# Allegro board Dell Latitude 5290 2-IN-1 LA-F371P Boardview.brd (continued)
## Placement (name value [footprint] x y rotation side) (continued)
PR280  100K_0402_5%  [R_0402]  148.26 120.72 0 top
PR281  100K_0402_5%  [R_0402]  148.13 117.16 0 top
PR282  549K_0402_1%  [R_0402]  145.67 117.78 90 top
PR283  100K_0402_5%  [R_0402]  148.51 125.03 0 top
PR284  100K_0402_5%  [R_0402]  149.43 124.14 180 top
PR285  1M_0402_1%  [R_0402]  145.68 119.64 180 top
PR300  0.01_1206_1%  [R_1206_4P-D]  123.97 99.57 180 top
PR301  3.3_0402_1%  [R_0402]  129.21 127.19 0 bottom
PR302  3.3_0402_1%  [R_0402]  129.21 128.08 0 bottom
PR303  2_1206_5%  [R_1206]  126.87 131.13 0 bottom
PR305  442K_0402_1%  [R_0402]  132.89 132.65 0 bottom
PR306  2.2_0603_5%  [R_0603]  129.73 125.92 0 bottom
PR307  100K_0402_1%  [R_0402]  133.81 131.76 180 bottom
PR308  4.7_0402_5%  [R_0402]  132.77 129.61 0 top
PR309  2_1206_5%  [R_1206]  135.95 131.13 180 top
PR310  0.005_1206_1%  [R_1206_4P-D]  139.31 119.06 0 top
PR311  2.2_0603_5%  [R_0603]  133.73 122.56 270 bottom
PR312  154K_0402_1%  [R_0402]  153.56 123.8 180 top
PR313  0_0402_5%  [R_0402]  136.59 131.71 270 bottom
PR314  0_0402_5%  [R_0402]  137.48 131.71 270 bottom
PR315  75_0402_5%  [R_0402]  138.37 131.71 270 bottom
PR316  4.7_1206_5%  [R_1206]  134.37 104.52 270 bottom
PR317  4.7_1206_5%  [R_1206]  127.51 116.71 90 bottom
PR318  0_0402_5%  [R_0402]  135.13 123.08 270 top
PR319  100K_0402_1%  [R_0402]  134.92 129.54 0 top
PR322  105K_0402_1%  [R_0402]  139.24 128.59 0 bottom
PR323  2.2_0402_1%  [R_0402]  137.1 120.89 90 bottom
PR324  2.2_0402_1%  [R_0402]  137.99 120.89 90 bottom
PR325  1M_0402_1%  [R_0402]  140.16 130.37 180 bottom
PR327  499_0402_1%  [R_0402]  139.26 126.76 270 bottom
PR328  1K_0402_1%  [R_0402]  31.02 123.3 270 bottom
PR329  0_0402_5%  [R_0402]  139.26 124.98 270 bottom
PR330  100_0402_1%  [R_0402]  139.24 124.53 0 top
PR331  0_0402_5%  [R_0402]  132.89 130.86 0 bottom
PR332  0_0402_5%  [R_0402]  140.16 129.48 180 bottom
PR333  10K_0402_5%  [R_0402]  53.35 158.72 270 bottom
PR334  0_0402_5%  [R_0402]  135.59 131.75 270 bottom
PR336  1M_0402_1%  [R_0402]  154.69 128.34 270 top
PR338  0_0402_5%  [R_0402]  152.62 128.46 0 top
PR341  0_0402_5%  [R_0402]  136.72 129.17 270 top
PR342  0_0402_5%  [R_0402]  153.96 118.71 90 top
PR343  0_0402_5%  [R_0402]  155.28 118.71 90 top
PR345  0_0402_5%  [R_0402]  154.69 123.59 90 top
PR346  100K_0402_1%  [R_0402]  158.41 124.47 270 top
PR347  1M_0402_1%  [R_0402]  152.6 122.59 270 top
PR351  0_0402_5%  [R_0402]  158.41 126.28 270 top
PR400  10_0603_5%  [R_0603]  70.68 74.87 180 top
PR401  0_0402_5%  [R_0402]  79.49 81.83 0 top
PR402  0_0402_5%  [R_0402]  77.71 82.72 0 top
PR403  0_0402_5%  [R_0402]  78.55 80.35 180 top
PR404  0_0402_5%  [R_0402]  77.71 83.61 0 top
PR405  523K_0402_1%  [R_0402]  78.55 77.92 180 top
PR406  43K_0201_1%  [R_0201]  78.46 78.69 180 top
PR407  10K_0402_1%  [R_0402]  70.31 87.95 180 top
PR408  1M_0402_1%  [R_0402]  69.39 85.28 0 top
PR409  0_0402_5%  [R0402_0OHM]  69.39 87.06 0 top
PR410  1M_0402_1%  [R_0402]  69.39 79.06 0 top
PR411  0_0402_5%  [R_0402]  79.49 82.72 0 top
PR412  45.3K_0402_1%  [R_0402]  70.31 79.95 180 top
PR413  1M_0402_1%  [R_0402]  77.64 79.45 0 top
PR414  953K_0402_1%  [R_0402]  70.31 80.84 180 top
PR415  118K_0402_1%  [R_0402]  70.31 81.73 180 top
PR416  0_0402_5%  [R0402_0OHM]  70.31 84.39 180 top
PR417  0_0402_5%  [R0402_0OHM]  72.21 85.92 180 top
PR418  0_0402_5%  [R_0402]  72.21 85.03 180 top
PR419  0_0402_5%  [R_0402]  70.31 83.5 180 top
PR420  0_0402_5%  [R_0402]  73.96 85.92 0 top
PR500  0_0402_5%  [R0402_0OHM]  123.33 119.83 180 top
PR501  3.3_0603_1%  [R_0603]  121.86 115.25 0 top
PR502  4.7_0805_5%  [R_0805]  119.25 114.78 90 bottom
PR503  100K_0402_5%  [R_0402]  116.4 119.5 90 top
PR504  0_0402_5%  [R_0402]  123.32 118.04 90 top
PR505  2.2K_0402_1%  [R_0402]  123.33 117.98 180 bottom
PR506  0_0402_5%  [R_0402]  41.71 150.69 0 top
PR507  3.3_0603_1%  [R_0603]  42.86 155.39 180 top
PR508  4.7_0805_5%  [R_0805]  45.5 156.15 0 bottom
PR509  100K_0402_5%  [R_0402]  48.9 153.4 90 top
PR510  0_0402_5%  [R_0402]  41.71 151.58 0 top
PR511  0_0402_5%  [R0402_0OHM]  123.9 146.29 180 top
PR512  3.3_0603_1%  [R_0603]  122.56 141.59 0 top
PR513  4.7_0805_5%  [R_0805]  118.36 141.63 90 bottom
PR514  100K_0402_5%  [R_0402]  117.35 147.23 90 top
PR515  0_0402_5%  [R_0402]  123.89 144.45 90 top
PR516  100K_0402_1%  [R_0402]  122.43 118.95 270 top
PR517  100K_0402_1%  [R_0402]  42.62 152.47 180 top
PR518  100K_0402_1%  [R_0402]  123 145.37 270 top
PR519  0_0402_5%  [R_0402]  116.4 115.56 90 top
PR600  75_0402_5%  [R_0402]  108.75 120.16 270 bottom
PR601  2.2_0603_5%  [R_0603]  110.68 117.16 0 top
PR602  4.7_0805_5%  [R_0805]  107.19 118.72 90 bottom
PR603  100K_0402_1%  [R_0402]  111.84 119.19 180 top
PR604  100K_0402_1%  [R_0402]  110.92 120.08 0 top
PR605  0_0402_5%  [R_0402]  109.09 123.33 270 bottom
PR606  100K_0402_5%  [R_0402]  103.56 121.6 0 top
PR607  1M_0402_1%  [R_0402]  108.2 122.42 90 bottom
PR608  0_0402_5%  [R_0402]  109.98 123.33 270 bottom
PR609  150K_0402_1%  [R_0402]  110.92 120.97 0 top
PR610  0_0402_5%  [R0402_0OHM]  104.47 122.49 180 top
PR611  0_0402_5%  [R_0402]  111.84 123.64 180 top
PR612  1M_0402_1%  [R_0402]  110.92 122.75 0 top
PR700  75K_0402_1%  [R_0402]  133.73 137.66 90 top
PR701  1M_0402_1%  [R_0402]  132.84 138.57 270 top
PR702  4.7_0603_5%  [R_0603]  127.83 143.13 90 bottom
PR703  0_0603_5%  [R_0603]  125.35 142.18 90 top
PR704  14K_0402_1%  [R_0402]  132.79 141.73 180 bottom
PR705  100K_0402_5%  [R_0402]  129.46 137.1 0 top
PR706  20K_0402_1%  [R_0402]  131.88 139.96 0 bottom
PR707  100K_0402_5%  [R_0402]  132.85 140.34 180 top
PR708  0_0402_5%  [R_0402]  132.85 139.45 180 top
PR709  0_0402_5%  [R0402_0OHM]  132.85 141.23 180 top
PR720  0_0402_5%  [R_0402]  142.82 141.8 180 top
PR721  0_0402_5%  [R_0402]  142.82 142.69 180 top
PR722  412K_0402_1%  [R_0402]  135.05 142.43 0 top
PR723  4.7_0603_5%  [R_0603]  139 144.34 180 bottom
PR724  324K_0402_1%  [R_0402]  135.95 141.56 270 top
PR725  100K_0402_5%  [R_0402]  134.11 142.13 270 top
PR726  0_0402_5%  [R0402_0OHM]  135.06 140.64 90 top
PR727  0_0402_5%  [R_0402]  105.36 98.36 180 top
PR728  0_0402_5%  [R_0402]  104.44 97.47 0 top
PR729  412K_0402_1%  [R_0402]  112.22 96.33 180 top
PR730  4.7_0805_5%  [R_0805]  106.93 93.12 270 top
PR731  324K_0402_1%  [R_0402]  111.32 95.45 270 top
PR732  100K_0402_5%  [R_0402]  111.3 93.66 0 top
PR733  0_0402_5%  [R0402_0OHM]  111.3 97.22 0 top
PR734  100K_0402_5%  [R_0402]  119 124.6 270 top
PR735  100K_0402_5%  [R_0402]  46.43 142.43 180 top
PR800  10K_0402_1%  [R_0402]  123.19 131.71 270 top
PR801  0_0402_5%  [R_0402]  122.3 131.71 270 top
PR803  1M_0402_1%  [R_0402]  124.97 130.8 90 top
PR804  10K_0402_1%  [R_0402]  127.71 126.18 180 top
PR805  10K_0402_1%  [R_0402]  126.06 126.05 180 bottom
PR806  4.7_0603_5%  [R_0603]  120.97 126.18 0 bottom
PR807  100_0402_1%  [R_0402]  120.27 123.69 90 top
PR808  10K_0402_1%  [R_0402]  124.28 126.05 180 bottom
PR809  10K_0402_1%  [R_0402]  126.8 125.29 0 top
PR810  0_0402_5%  [R0402_0OHM]  121.16 124.6 270 top
PR811  0_0402_5%  [R0402_0OHM]  122.05 124.6 270 top
PR812  100_0402_1%  [R_0402]  122.94 124.6 270 top
PR813  10K_0402_1%  [R_0402]  48.45 147.75 90 top
PR814  0_0402_5%  [R_0402]  49.34 148.67 270 top
PR815  130K_0402_1%  [R_0402]  51.19 149.54 180 top
PR816  1M_0402_1%  [R_0402]  50.28 148.66 0 top
PR817  10K_0402_1%  [R_0402]  52.83 140.83 90 top
PR818  10K_0402_1%  [R_0402]  53.54 142.69 180 top
PR819  4.7_0603_5%  [R_0603]  48.13 145.67 90 bottom
PR820  10K_0402_1%  [R_0402]  51.05 141.75 270 top
PR821  10K_0402_1%  [R_0402]  52.63 144.46 0 top
PR822  0_0402_5%  [R_0402]  53.54 143.58 180 top
PR823  0_0402_5%  [R_0402]  51.94 140.83 90 top
PR824  0_0402_5%  [R0402_0OHM]  48.4 141.73 180 top
PR825  100K_0402_1%  [R_0402]  49.28 141.75 270 top
PR826  0_0402_5%  [R_0402]  124.63 133.16 0 top
PR900  45.3_0402_1%  [R_0402]  63.42 145.98 90 bottom
PR901  75_0402_1%  [R_0402]  59.97 145.98 90 bottom
PR903  0_0402_5%  [R_0402]  62.06 158.92 90 bottom
PR904  0_0402_5%  [R_0402]  62.93 158.92 90 bottom
PR906  0_0402_5%  [R_0402]  64.66 158.94 0 bottom
PR907  0_0402_5%  [R_0402]  65.1 157.18 90 bottom
PR910  1.5K_0402_1%  [R_0402]  60.29 158.47 90 bottom
PR911  1.5K_0402_1%  [R_0402]  59.42 158.47 90 bottom
PR912  1.5K_0402_1%  [R_0402]  58.56 158.47 90 bottom
PR913  1.5K_0402_1%  [R_0402]  57.7 158.47 90 bottom
PR914  1.91K_0402_1%  [R_0402]  61.15 158.92 90 bottom
PR915  2.49K_0402_1%  [R_0402]  63.82 159.83 270 bottom
PR916  0_0402_5%  [R_0402]  54.76 152.7 0 bottom
PR917  10K_0402_1%  [R_0402]  56.51 147.73 90 bottom
PR918  10K_0402_1%  [R_0402]  57.38 147.73 90 bottom
PR919  10K_0402_1%  [R_0402]  58.24 147.73 90 bottom
PR920  10K_0402_1%  [R_0402]  54.76 151.83 0 bottom
PR921  0_0402_5%  [R_0402]  55.63 149.51 0 bottom
PR922  0_0402_5%  [R_0402]  56.45 145.98 90 bottom
PR923  0_0402_5%  [R_0402]  57.34 145.98 90 bottom
PR924  0_0402_5%  [R_0402]  63.42 148.64 270 bottom
PR925  100_0402_1%  [R_0402]  62.56 145.98 90 bottom
PR926  0_0402_5%  [R_0402]  60.83 147.73 90 bottom
PR927  49.9_0402_1%  [R_0402]  62.56 147.73 90 bottom
PR928  10_0402_1%  [R_0402]  61.7 147.73 90 bottom
PR929  0_0402_5%  [R_0402]  61.7 145.98 90 bottom
PR930  0_0402_5%  [R_0402]  60.83 145.98 90 bottom
PR931  1.91K_0402_1%  [R_0402]  59.11 147.73 90 bottom
PR932  0_0402_5%  [R_0402]  59.97 147.73 90 bottom
PR933  75_0402_5%  [R_0402]  58.24 145.98 90 bottom
PR934  10K_0402_1%  [R_0402]  59.11 145.98 90 bottom
PR935  0_0402_5%  [R_0402]  64.29 147.73 90 bottom
PR936  0_0402_5%  [R_0402]  66.32 150.21 180 bottom
PR937  10K_0402_1%  [R_0402]  65.42 148.42 90 bottom
PR938  5.23K_0402_1%  [R_0402]  55.94 156.72 90 bottom
PR939  0_0402_5%  [R_0402]  53.9 149.51 0 bottom
PR940  10K_0402_1%  [R_0402]  55.65 148.63 180 bottom
PR941  118K_0402_1%  [R_0402]  68.1 154.91 180 bottom
PR942  133K_0402_1%  [R_0402]  55.1 159.58 180 bottom
PR943  2M_0402_5%  [R_0402]  56.83 158.47 90 bottom
PR944  121K_0402_1%  [R_0402]  68.1 154.02 180 bottom
PR945  620K_0402_1%  [R_0402]  66.32 151.98 180 bottom
PR946  49.9K_0402_1%  [R_0402]  55.1 156.99 180 bottom
PR947  0_0402_5%  [R_0402]  54.72 154.93 0 bottom
PR948  8.06K_0402_1%  [R_0402]  65.98 157.83 0 bottom
PR949  0_0402_5%  [R_0402]  54.19 158.72 0 bottom
PR950  4.7_0402_5%  [R_0402]  55.65 147.74 180 bottom
PR951  0_0402_5%  [R_0402]  65.41 155.79 0 bottom
PR952  0_0402_5%  [R_0402]  65.41 154.91 0 bottom
PR953  100K_0402_1%  [R_0402]  60.3 160.24 180 bottom
PR954  100K_0402_1%  [R_0402]  64.67 159.83 0 bottom
PR955  100K_0402_1%  [R_0402]  67.31 156.75 0 bottom
PR956  61.9K_0402_1%  [R_0402]  66.32 151.1 180 bottom
PR1101  0_0402_5%  [R_0402]  79.69 159.78 270 top
PR1103  0_0402_5%  [R_0402]  62.8 159.84 270 top
PR1106  4.7_0805_5%  [R_0805]  89.7 157.29 0 top
PR1108  4.7_0805_5%  [R_0805]  72.97 157.18 90 top
PR1117  4.7_0805_5%  [R_0805]  101.33 155.69 0 top
PR1118  0_0402_5%  [R_0402]  93.28 158.83 270 top
PR1125  4.7_0805_5%  [R_0805]  54.55 152.19 270 top
PR1126  0_0402_5%  [R_0402]  52.96 156.29 270 top
PR1200  1K_0402_1%  [R_0402]  94.61 145.34 90 top
PR1201  1K_0402_1%  [R_0402]  110.41 147.19 0 top
PR1202  1K_0402_1%  [R_0402]  56.02 144.21 180 top
PR1203  0_0805_5%  [R_0805]  47.35 149.87 180 bottom
PR1204  0_0603_5%  [R_0603]  53.49 149.09 270 top
PT100  PAD~D  [TPC12]  121.91 101.4 0 top
PT101  PAD~D  [TPC12]  8.01 39.1 180 bottom
PT102  PAD~D  [TPC12]  13.97 32.45 180 bottom
PT103  PAD~D  [TPC12]  152.7 119.39 0 top
PU101  -  [RT9069-33GB_SOT23-5]  16.26 48.73 270 top
PU103  -  [AS331KTR-G1_SOT23-5]  26.54 49.09 270 top
PU104  -  [AS331KTR-G1_SOT23-5]  36.92 41.85 90 top
PU105  -  [AS331KTR-G1_SOT23-5]  34.54 19.12 90 top
PU280  -  [SN74LVC1G123DCUR_VSSOP8]  150 118.19 90 top
PU300  -  [ISL88738HRTZ-T_TQFN32_4X4]  136.78 124.51 90 bottom
PU301  TC7SH08FU_SSOP5  [MC74VHC1G08DFT2G_SC70-5]  155.97 123.75 0 top
PU400  TPS61188ARUYR_QFN28_4X4  [TPS61188ARUYR_QFN28_4X4-S]  75.89 79.3 90 top
PU500  -  [NB680GD-Z_QFN12_2X3]  119.75 118.44 270 top
PU501  -  [NB679AGD-Z_QFN12_2X3]  45.35 153.39 90 top
PU502  -  [NB679GD-Z_QFN12_2X3]  120.32 145.38 270 top
PU600  -  [NB685GQ-Z_QFN16_3X3]  108.18 120.3 270 top
PU700  -  [SY8286RAC_QFN20_3X3]  127.23 141.05 0 top
PU720  TLV62150ARGTR_QFN16_3X3  [TLV62150RGTR_QFN16_3X3-S]  139.78 143.21 180 top
PU721  TLV62150RGTR_QFN16_3X3  [TLV62150RGTR_QFN16_3X3-S]  107.49 94.9 0 top
PU800  TPS62134ARGT_QFN16_3X3  [TPS62134ARGT_QFN16_3X3-S]  122.23 128.27 0 top
PU801  TPS62134DRGT_QFN16_3X3  [TPS62134BRGT_QFN16_3X3-S]  47.98 145.47 0 top
PU900  MP2949AGQKT-0020  [MP2949GU-LF-Z_QFN48_6X6]  58.56 157.22 270 bottom
PU1005  -  [MP86901-CGLT-Z_TQFN21_3X4]  82.85 158.78 90 top
PU1006  -  [MP86901-CGLT-Z_TQFN21_3X4]  65.96 158.81 90 top
PU1107  -  [MP86901-CGLT-Z_TQFN21_3X4]  95.5 156.06 90 top
PU1108  -  [MP86901-AGQT-Z_TQFN13_3X3]  56.09 155.28 90 top
Q1  -  [DMN2400UV-7_SOT-563-6]  119.74 158.35 180 bottom
Q2  -  [MMBT3904WH_SOT323-3]  5.54 164.78 0 top
Q6  -  [MMBT3904WH_SOT323-3]  143.57 113.68 180 bottom
Q7  -  [MMBT3904WH_SOT323-3]  44.83 84.74 180 top
Q8  -  [MMBT3904WH_SOT323-3]  21.97 17.93 180 top
Q9  -  [DMN2400UV-7_SOT-563-6]  155.23 146.5 90 bottom
Q10  DII-DMN65D8LW-7  [SSM3K7002FU_SC70-3]  63.5 100.21 180 bottom
Q11  -  [MMBT3904WH_SOT323-3]  65.75 111.08 180 bottom
Q12  DII-DMN65D8LW-7  [SSM3K7002FU_SC70-3]  25.6 125.25 0 bottom
Q16  DII-DMN65D8LW-7  [SSM3K7002FU_SC70-3]  52.26 85.54 90 top
Q22  DII-DMN65D8LW-7  [SSM3K7002FU_SC70-3]  26.4 135.38 270 bottom
Q25  -  [DMN2400UV-7_SOT-563-6]  28.38 127.14 180 bottom
Q26  -  [DMN2400UV-7_SOT-563-6]  124.88 155.01 90 bottom
Q29  DII-DMN65D8LW-7  [SSM3K7002FU_SC70-3]  33.64 109.46 0 top
Q31  -  [MMBT3904WH_SOT323-3]  45.42 103.68 180 bottom
Q32  DII-DMN65D8LW-7  [SSM3K7002FU_SC70-3]  83.72 73.06 90 top
Q33  SI3457BDV-T1-E3_TSOP6~D  [SI3457BDV-T1-E3_TSOP6]  84.52 75.13 90 top
Q348  DII-DMN65D8LW-7  [SSM3K7002FU_SC70-3]  28.19 93.36 180 bottom
Q349  -  [DMG2301U-7_SOT23-3]  30.68 97.09 90 bottom
Q351  DII-DMN65D8LW-7  [SSM3K7002FU_SC70-3]  66.29 85.33 90 top
Q352  -  [DMG2301U-7_SOT23-3]  56.16 103.51 270 bottom
Q353  DII-DMN65D8LW-7  [SSM3K7002FU_SC70-3]  51.6 104.87 180 bottom
Q354  -  [DMN2400UV-7_SOT-563-6]  126.91 92.06 90 top
Q356  DII-DMN65D8LW-7  [SSM3K7002FU_SC70-3]  47.24 84.77 0 top
Q357  DII-DMN65D8LW-7  [SSM3K7002FU_SC70-3]  24.41 93.38 90 bottom
QC2  -  [DMN66D0LDW-7_SOT363-6]  29.72 37.78 270 top
QC3  -  [DMN66D0LDW-7_SOT363-6]  29.91 25.83 90 top
QE13  -  [DMN66D0LDW-7_SOT363-6]  136.87 137.67 180 top
QE14  -  [DMN66D0LDW-7_SOT363-6]  16.7 102.41 90 bottom
QE15  DII-DMN65D8LW-7  [SSM3K7002FU_SC70-3]  21.59 122.74 0 bottom
QE16  -  [MMBT3904WH_SOT323-3]  17.26 122.35 180 bottom
QR1  -  [DMN2400UFB4-7_DFN1006H4-3]  68.2 29.12 270 bottom
QZ9  -  [DMG2301U-7_SOT23-3]  29.97 101.79 90 bottom
R1  0_0402_1%  [R0402_0OHM]  117.78 171.9 0 top
R2  0_0402_1%  [R0402_0OHM]  117.78 170.88 0 top
R3  100K_0201_5%  [R_0201]  126.36 169.06 90 top
R4  0_0402_1%  [R0402_0OHM]  117.78 168.85 0 top
R5  100K_0201_5%  [R_0201]  127 169.06 90 top
R6  0_0402_1%  [R0402_0OHM]  117.78 169.86 0 top
R7  0_0402_1%  [R0402_0OHM]  117.78 166.69 0 top
R8  0_0402_1%  [R0402_0OHM]  117.78 167.83 0 top
R9  0_0402_1%  [R0402_0OHM]  117.53 156.4 0 top
R11  0_0201_5%  [R0201_0OHM]  125.5 161.81 0 top
R12  0_0402_1%  [R0402_0OHM]  117.53 155.39 0 top
R13  0_0402_1%  [R0402_0OHM]  117.53 158.43 0 top
R14  100K_0201_5%  [R_0201]  126.1 160.59 180 top
R15  100K_0201_5%  [R_0201]  125.44 154.9 0 top
R16  0_0402_1%  [R0402_0OHM]  117.53 157.42 0 top
R17  0_0402_1%  [R0402_0OHM]  117.53 162.5 0 top
R18  0_0402_1%  [R0402_0OHM]  117.53 161.48 0 top
R19  0_0402_1%  [R0402_0OHM]  117.53 160.47 0 top
R20  0_0402_1%  [R0402_0OHM]  117.53 159.45 0 top
R21  0_0402_1%  [R0402_0OHM]  117.53 164.53 0 top
R22  0_0402_1%  [R0402_0OHM]  117.53 163.51 0 top
R23  1K_0201_5%  [R_0201]  6.26 153.48 180 top
R24  1K_0201_5%  [R_0201]  6.39 140.15 180 top
R26  0_0402_1%  [R0402_0OHM]  66.09 138.88 0 top
R27  10K_0402_5%~D  [R_0402]  152.74 137.67 180 top
R28  10K_0402_5%~D  [R_0402]  153.67 139.5 180 top
R29  10K_0402_5%~D  [R_0402]  152.78 135.37 90 top
R30  0_0603_5%  [R0603_0OHM]  128.71 135.32 0 top
R31  100K_0402_5%~D  [R_0402]  122.61 134.05 0 top
R32  100K_0402_5%  [R_0402]  101.66 118.82 270 top
R33  10K_0201_1%  [R_0201]  27.52 112.33 0 top
R35  10K_0201_1%  [R_0201]  34.29 112.41 180 top
R38  0_0402_1%  [R0402_0OHM]  29.79 112.46 180 top
R48  0_0603_5%  [R0603_0OHM]  68.22 104.46 0 top
R50  100K_0402_5%  [R_0402]  31.83 102.94 180 top
R51  1M_0402_5%  [R_0402]  33.45 102.94 0 top
R54  10K_0402_5%  [R_0402]  36.91 100.78 180 top
R56  23.2K_0402_1%  [R_0402]  33.29 96.97 180 top
R57  0_0402_5%  [R_0402]  61.19 86.6 90 top
R59  0_0402_1%  [R0402_0OHM]  59.21 86.37 270 top
R60  0_0402_1%  [R0402_0OHM]  60.22 86.37 270 top
R61  220K_0201_5%  [R_0201]  70.99 87.76 270 top
R64  10K_0402_5%  [R_0402]  61.16 85.74 270 top
R65  0_0402_5%  [R_0402]  62.05 84.82 90 top
R66  0_0402_1%  [R0402_0OHM]  57.61 87.85 0 top
R67  4.7K_0201_5%  [R_0201]  79.49 84.41 0 top
R72  0_0805_5%  [R0805_0OHM]  70.9 60.14 0 top
R73  100K_0201_5%  [R_0201]  69.18 54.04 0 top
R74  100K_0201_5%  [R_0201]  71.03 54.04 180 top
R75  0_0603_5%  [R0603_0OHM]  38.73 20.32 90 bottom
R76  220K_0201_5%  [R_0201]  37.47 21.24 90 top
R77  470K_0402_5%  [R_0402]  140.97 137.43 270 bottom
R78  560K_0402_5%  [R_0402]  141.86 136.51 90 bottom
R79  0_0603_5%  [R0603_0OHM]  143.89 137.42 270 bottom
R81  0_0201_5%  [R0201_0OHM]  110.3 165.38 90 top
R82  0_0201_5%  [R0201_0OHM]  111.51 165.97 270 top
R83  0_0201_5%  [R_0201]  113.39 169.36 180 top
R84  0_0201_5%  [R_0201]  112.8 167.64 0 top
R85  0_0201_5%  [R_0201]  112.8 168.21 0 top
R86  0_0201_5%  [R_0201]  112.8 167.07 0 top
R87  0_0201_5%  [R_0201]  112.8 168.78 0 top
R88  0_0201_5%  [R_0201]  113.39 166.5 180 top
R90  0_0603_5%  [R0603_0OHM]  146.49 148.78 0 bottom
R91  100K_0201_5%  [R_0201]  157.65 148.4 180 bottom
R92  0_0201_5%  [R_0201]  155.79 148.4 0 bottom
R93  100K_0201_5%  [R_0201]  154.52 148.4 0 bottom
R94  0_0603_5%  [R0603_0OHM]  143.83 148.27 0 bottom
R95  8.2K_0201_5%  [R_0201]  153.58 148.15 180 bottom
R96  0_0201_5%  [R_0201]  154.32 147.22 90 bottom
R97  0_0201_5%  [R_0201]  157.73 147.04 270 bottom
R98  0_0603_5%  [R0603_0OHM]  149.1 145.54 90 bottom
R99  0_0201_5%  [R_0201]  153.8 145.82 0 bottom
R100  8.2K_0201_5%  [R_0201]  151.89 145.57 90 bottom
R101  0_0402_1%  [R0402_0OHM]  144.96 145.73 0 bottom
R102  0_0603_5%  [R0603_0OHM]  147.76 144.59 180 bottom
R104  1M_0402_5%  [R_0402]  153.54 143.24 90 bottom
R105  0_0603_5%  [R0603_0OHM]  147.76 143.32 180 bottom
R106  0_0603_5%  [R0603_0OHM]  147.76 142.05 180 bottom
R107  0_0402_5%  [R_0402]  155.27 140.91 180 bottom
R108  0_0402_5%  [R_0402]  155.27 139.89 180 bottom
R109  100K_0402_5%~D  [R_0402]  36.31 137.03 0 bottom
R110  100K_0402_5%~D  [R_0402]  36.31 137.92 0 bottom
R111  0_0603_5%  [R0603_0OHM]  22.61 138.3 90 bottom
R112  0_0603_5%  [R0603_0OHM]  18.54 137.16 90 bottom
R113  0_0603_5%  [R0603_0OHM]  152.97 139.51 270 bottom
R114  0_0805_5%  [R0805_0OHM]  30.84 138.56 0 bottom
R115  0_0402_1%  [R0402_0OHM]  151.03 136.91 180 bottom
R116  0_0603_5%  [R0603_0OHM]  147.89 137.48 180 bottom
R117  100K_0402_5%~D  [R_0402]  37.22 135.26 180 bottom
R118  0_0603_5%  [R0603_0OHM]  51.18 136.91 90 bottom
R119  0_0603_5%  [R0603_0OHM]  31.18 134.81 180 bottom
R120  0_0603_5%  [R0603_0OHM]  53.66 131.26 0 bottom
R121  0_0201_5%  [R_0201]  60.33 125.33 270 bottom
R122  0_0402_1%  [R0402_0OHM]  19.3 125.36 270 bottom
R123  100K_0402_5%  [R_0402]  32.84 124.4 180 bottom
R124  0_0201_5%  [R_0201]  17.65 125.71 270 bottom
R125  0_0201_5%  [R_0201]  29.84 124.07 180 bottom
R139  100K_0402_5%~D  [R_0402]  20.7 89.68 270 bottom
R140  0_0805_5%  [R0805_0OHM]  21.51 83.55 0 bottom
R145  0_0805_5%  [R0805_0OHM]  48.86 89.22 180 bottom
R146  100K_0402_5%~D  [R_0402]  55.75 88.79 270 bottom
R147  0_0402_5%  [R_0402]  53.98 88.79 270 bottom
R148  0_0402_5%  [R_0402]  54.86 88.79 270 bottom
R149  0_0402_5%  [R_0402]  55.77 87 180 bottom
R150  0_0402_5%  [R_0402]  53.98 86.09 90 bottom
R151  100K_0402_5%~D  [R_0402]  55.77 86.11 180 bottom
R152  0_0805_5%  [R0805_0OHM]  48.98 85.54 180 bottom
R153  0.01_0603_1%  [R_0603]  43.48 90.06 90 bottom
R154  15K_0402_1%  [R_0402]  40.13 79.11 90 bottom
R155  51_0402_5%  [R_0402]  41.02 77.33 90 bottom
R156  100K_0402_5%  [R_0402]  20.19 63.11 90 bottom
R157  100K_0402_5%  [R_0402]  19.89 62.17 180 bottom
R158  220K_0201_5%  [R_0201]  20.19 64.8 90 bottom
R159  220K_0201_5%  [R_0201]  19.1 62.98 90 bottom
R160  100K_0201_5%  [R_0201]  19.6 56.71 180 bottom
R161  0_0402_1%  [R0402_0OHM]  20.19 67.43 90 bottom
R204  0_0603_5%  [R0603_0OHM]  75.06 25.4 90 bottom
R205  0_0603_5%  [R0603_0OHM]  71.88 25.4 90 bottom
R209  100K_0402_5%~D  [R_0402]  73.91 18.1 270 bottom
R210  100K_0402_5%~D  [R_0402]  72.14 20.08 270 bottom
R211  100K_0402_5%~D  [R_0402]  71.25 20.08 270 bottom
R214  10K_0402_1%  [R_0402]  17.97 126.48 90 bottom
R215  49.9K_0402_1%  [R_0402]  18.86 126.48 90 bottom
R216  100K_0402_5%~D  [R_0402]  19.81 89.68 270 bottom
R217  100K_0402_5%~D  [R_0402]  23.61 126.05 0 bottom
R218  0_0402_5%  [R_0402]  24.52 127.83 180 bottom
R219  0_0402_1%  [R0402_0OHM]  21.09 125.1 180 bottom
R223  0_0603_5%  [R0603_0OHM]  27.56 101.79 180 bottom
R233  49.9K_0402_1%  [R_0402]  52.4 103.7 180 bottom
R234  499K_0402_1%  [R_0402]  54.24 105.98 180 bottom
R235  100K_0402_5%  [R_0402]  53.33 106.87 0 bottom
R266  0_0603_5%  [R0603_0OHM]  12.83 97.41 270 top
R275  0.0002_0805_5%  [R_0805]  79.86 127.32 0 bottom
R276  0.0002_0805_5%  [R_0805]  81.56 121.1 0 bottom
R277  0.0002_0805_5%  [R_0805]  79.86 121.1 0 bottom
R278  0.0002_0805_5%  [R_0805]  81.56 127.32 0 bottom
R279  0_0402_5%  [R_0402]  84.02 119.7 180 bottom
R280  0_0402_5%  [R_0402]  83.74 129.86 0 bottom
R411  100_0402_5%  [R_0402]  49.78 88.25 270 top
R412  0_0402_1%  [R0402_0OHM]  76.39 36.95 90 bottom
R413  0_0402_1%  [R0402_0OHM]  77.28 36.95 90 bottom
R414  0_0402_1%  [R0402_0OHM]  79.12 36.95 90 bottom
R415  0_0402_1%  [R0402_0OHM]  78.23 36.95 90 bottom
R416  0_0402_1%  [R0402_0OHM]  80.96 36.95 90 bottom
R417  0_0402_1%  [R0402_0OHM]  80.07 36.95 90 bottom
R418  0_0402_5%  [R_0402]  77.05 25.22 180 bottom
R419  0_0402_1%  [R0402_0OHM]  77.79 22.77 0 bottom
R420  0_0402_1%  [R0402_0OHM]  77.79 21.88 0 bottom
R421  0_0402_1%  [R0402_0OHM]  77.79 20.99 0 bottom
R425  0.01_0603_1%  [R_0603]  18.86 128.46 180 bottom
R427  0_0402_5%  [R_0402]  29.39 127.76 0 bottom
R428  0_0201_5%  [R_0201]  127.38 155.42 270 bottom
R429  0_0201_5%  [R_0201]  124.08 155.42 270 bottom
R430  100K_0201_5%  [R_0201]  127.38 156.69 270 bottom
R431  100K_0201_5%  [R_0201]  124.08 156.69 270 bottom
R432  0_0402_1%  [R0402_0OHM]  77.79 20.09 0 bottom
R433  0_0402_1%  [R0402_0OHM]  81.62 32.92 0 bottom
R434  0_0201_5%  [R_0201]  120.18 165.99 180 top
R435  0_0201_5%  [R_0201]  125.5 162.4 0 top
R438  0_0402_1%  [R0402_0OHM]  153.76 141.26 270 top
R439  10K_0402_5%  [R_0402]  44.02 89.09 180 bottom
R442  100K_0402_5%~D  [R_0402]  137.74 149.54 180 bottom
R443  0_0402_1%  [R0402_0OHM]  153.67 138.61 180 top
R444  0_0402_5%  [R_0402]  151.83 139.51 270 top
R445  0_0402_1%  [R0402_0OHM]  151.97 140.37 0 top
R446  0_0402_5%  [R_0402]  151.97 141.25 0 top
R447  0_0201_5%  [R_0201]  155.22 149.04 0 bottom
R448  0_0603_5%  [R_0603]  141.1 146.81 0 bottom
R449  100K_0402_5%  [R_0402]  17.36 104.67 90 bottom
R450  0_0402_1%  [R0402_0OHM]  32.64 93.41 0 bottom
R451  10K_0402_5%  [R_0402]  35.43 90.49 270 bottom
R453  0_0603_5%  [R_0603]  42.85 97.28 0 bottom
R454  0_0603_5%  [R0603_0OHM]  42.85 98.49 0 bottom
R455  0_0402_1%  [R0402_0OHM]  27.8 138.43 0 bottom
R456  0_0402_1%  [R0402_0OHM]  31.76 90.73 90 top
R457  0_0603_5%  [R0603_0OHM]  38.23 98.57 270 bottom
R460  0_0402_5%  [R_0402]  40.7 97.16 180 bottom
R464  0_0402_5%  [R_0402]  81.32 25.8 0 bottom
R465  0_0402_5%  [R_0402]  81.32 26.68 0 bottom
R466  0_0402_5%  [R_0402]  81.32 24.91 0 bottom
R467  0_0402_5%  [R_0402]  81.08 24.02 0 bottom
R468  0_0402_5%  [R_0402]  80.91 23.13 0 bottom
R470  0_0402_5%  [R_0402]  38.07 126.81 180 bottom
R471  0_0402_5%  [R_0402]  38.07 125.92 180 bottom
R472  80.6_0402_1%~D  [R_0402]  136.49 138.71 180 top
R473  200K_0402_1%  [R_0402]  135.76 134.76 0 top
R474  10K_0402_5%  [R_0402]  45.03 104.79 0 bottom
R475  0_0402_1%  [R0402_0OHM]  19.62 103.34 270 bottom
R476  0_0402_1%  [R0402_0OHM]  33.4 104.84 180 bottom
R477  0_0201_5%  [R0201_0OHM]  150.7 140.71 90 top
R478  0_0201_5%  [R0201_0OHM]  151.27 140.71 90 top
R479  47K_0402_5%  [R_0402]  31.94 122.61 90 bottom
R480  220K_0201_5%  [R_0201]  46.04 101.2 270 bottom
R481  300K_0201_5%  [R_0201]  45.44 101.2 180 bottom
R484  0_0603_5%~D  [R_0603]  80.56 76.76 270 top
R485  1M_0402_5%~D  [R_0402]  82.84 78.37 0 top
R486  100K_0402_5%~D  [R_0402]  85.01 73.88 270 top
R487  5.1K_0201_1%  [R_0201]  154.38 146.46 180 bottom
R488  43K_0201_1%  [R_0201]  24.74 74.74 180 bottom
R489  0_0201_5%  [R_0201]  51.92 129.27 270 top
R490  100K_0201_5%  [R_0201]  24.16 76 0 bottom
R492  0_0201_5%  [R_0201]  24.22 70.5 270 bottom
R493  0_0201_5%  [R_0201]  23.62 70.5 270 bottom
R494  0_0201_5%  [R_0201]  23.04 70.5 270 bottom
R495  0_0402_5%  [R_0402]  80.91 22.06 0 bottom
R501  0_0603_5%~D  [R_0603]  81.84 79.81 180 top
R502  0_0603_5%~D  [R_0603]  81.84 78.54 180 top
R513  0_0201_5%  [R0201_0OHM]  16.31 109.02 0 bottom
R2745  100K_0201_1%  [R_0201]  29.08 97.78 270 bottom
R2751  0_0402_5%  [R_0402]  31.37 94.68 0 bottom
R5749  0_0402_1%  [R0402_0OHM]  29.39 121.55 270 bottom
R5750  0_0603_5%  [R0603_0OHM]  44.59 95.84 180 bottom
R5751  20K_0201_5%  [R_0201]  147.93 93.16 180 bottom
R5752  20K_0201_5%  [R_0201]  150.96 88.52 0 bottom
R5753  20K_0201_5%  [R_0201]  143.66 88.52 0 bottom
R5754  20K_0201_5%  [R_0201]  140.63 93.16 180 bottom
R5755  10K_0201_5%  [R_0201]  146.72 93.16 180 bottom
R5756  10K_0201_5%  [R_0201]  152.17 88.52 0 bottom
R5757  10K_0201_5%  [R_0201]  144.87 88.52 0 bottom
R5758  10K_0201_5%  [R_0201]  139.42 93.16 180 bottom
R5759  20K_0201_5%  [R_0201]  125.76 88.46 0 bottom
R5764  0_0402_5%  [R_0402]  73.91 19.12 90 bottom
R5765  0_0402_5%  [R_0402]  73.03 19.12 90 bottom
R5766  100_0402_5%  [R_0402]  48.88 88.25 270 top
R5767  10K_0201_5%  [R_0201]  127.55 88.46 180 bottom
R5768  10K_0402_5%  [R_0402]  30.73 93.79 180 bottom
R5769  1M_0402_5%~D  [R_0402]  26.52 96.79 90 bottom
R5770  0_0201_5%  [R0201_0OHM]  54.23 136.72 90 bottom
R5771  10K_0201_5%  [R_0201]  48.82 125.08 0 top
R5772  10K_0201_5%  [R_0201]  49.4 125.64 180 top
R5773  10K_0201_1%  [R_0201]  25.68 95.53 270 bottom
R5774  0_0201_5%  [R_0201]  29.29 128.82 0 bottom
R5775  10K_0201_5%  [R_0201]  42.43 128.54 0 top
R5776  10K_0201_5%  [R_0201]  43.01 129.11 180 top
R5777  10K_0402_5%  [R_0402]  43.56 123.31 0 top
R5778  0_0201_5%  [R_0201]  34.35 101.47 270 bottom
R5779  0_0201_5%  [R_0201]  27.28 97.23 90 bottom
R5780  100K_0402_5%~D  [R_0402]  71.17 83.83 180 bottom
R5781  0_0603_5%  [R0603_0OHM]  65.1 85.16 180 bottom
RA1  2.2K_0201_5%  [R_0201]  14.22 158.27 90 bottom
RA2  2.2K_0201_5%  [R_0201]  12.83 158.27 90 bottom
RA3  16.2_0402_1%  [R_0402]  8.43 158.94 0 bottom
RA6  16.2_0402_1%  [R_0402]  11.63 158.94 180 bottom
RA7  0_0201_5%  [R0201_0OHM]  7.2 161.36 0 bottom
RA8  0_0201_5%  [R_0201]  29.21 153.71 270 bottom
RA9  1K_0201_5%  [R_0201]  27.24 151.73 90 bottom
RA10  100K_0201_5%  [R_0201]  31.62 151.61 270 bottom
RA11  0_0402_1%  [R0402_0OHM]  18.97 144.85 0 bottom
RA12  0_0402_5%  [R_0402]  28.98 143.82 90 bottom
RA13  100K_0402_1%  [R_0402]  32.19 142.57 270 bottom
RA14  200K_0402_1%  [R_0402]  30.4 142.56 0 bottom
RA15  100K_0201_5%  [R_0201]  29.72 142.34 270 bottom
RA16  0_0402_5%  [R_0402]  23.75 142.38 270 bottom
RA17  33_0402_5%  [R_0402]  21.97 142.38 270 bottom
RA18  0_0402_5%  [R_0402]  18.34 142.43 0 bottom
RA19  100K_0201_5%  [R_0201]  24.98 141.04 0 bottom
RA21  1K_0201_5%  [R_0201]  33.59 143.55 270 bottom
RA22  0_0402_1%  [R0402_0OHM]  35.51 153.1 180 bottom
RA23  0_0402_1%  [R0402_0OHM]  17.56 144.9 90 bottom
RA24  22_0402_5%  [R_0402]  24.69 139 0 bottom
RA25  0_0402_1%  [R0402_0OHM]  11.3 155.06 90 bottom
RA26  0_0402_5%  [R_0402]  19.3 140.58 90 bottom
RA27  1K_0201_5%  [R_0201]  27.69 153.35 90 bottom
RA28  1K_0201_5%  [R_0201]  26.16 153.94 270 bottom
RA29  0_0402_5%  [R_0402]  27.88 139.32 90 bottom
RA30  1K_0201_5%  [R_0201]  26.54 152.31 270 bottom
RA31  0_0402_5%  [R_0402]  29.87 143.82 90 bottom
RA32  22_0402_5%  [R_0402]  24.69 138.11 0 bottom
RA33  10K_0402_5%  [R_0402]  31.99 143.45 0 bottom
RA36  0_0402_5%  [R_0402]  26.92 139.31 90 bottom
RA38  0_0402_1%  [R0402_0OHM]  68 21.4 0 bottom
RA39  10K_0402_5%  [R_0402]  68 20.51 0 bottom
RA40  100K_0201_5%  [R_0201]  31.28 143.45 180 bottom
RA41  0_0402_1%  [R0402_0OHM]  13.21 175.71 90 top
RA42  0_0402_1%  [R0402_0OHM]  5.5 130.49 0 top
RA43  0_0402_1%  [R0402_0OHM]  112.36 170.16 0 top
RA44  0_0201_5%  [R0201_0OHM]  126.06 163.62 270 top
RC1  0_0402_1%  [R0402_0OHM]  66.09 139.77 0 top
RC2  51_0402_5%  [R_0402]  85.09 139.94 90 top
RC3  1K_0402_5%  [R_0402]  86.11 140.86 270 top
RC5  100_0402_1%  [R_0402]  68.45 140.48 270 top
RC6  100_0402_1%  [R_0402]  69.34 139.56 90 top
RC7  49.9_0402_1%  [R_0402]  87.96 139.99 180 top
RC8  10K_0402_5%  [R_0402]  54.36 138.88 270 top
RC9  10K_0402_5%  [R_0402]  55.37 138.95 270 top
RC10  1.5K_0402_5%  [R_0402]  56.39 138.04 90 top
RC11  10K_0402_5%  [R_0402]  59.05 138.04 90 top
RC12  10K_0402_5%  [R_0402]  57.28 138.04 90 top
RC13  10K_0402_5%  [R_0402]  58.17 138.04 90 top
RC14  10K_0402_5%  [R_0402]  59.94 138.04 90 top
RC15  0_0402_5%  [R_0402]  60.86 138.95 270 top
RC16  0_0402_5%  [R_0402]  62.64 138.95 270 top
RC17  51_0402_5%  [R_0402]  85.09 138.95 270 top
RC18  51_0402_5%  [R_0402]  86.11 138.95 270 top
RC19  100_0402_5%  [R_0402]  87 138.95 270 top
RC20  1K_0402_5%  [R_0402]  88.01 139 270 top
RC21  0_0402_5%~D  [R_0402]  89.12 138.67 90 top
RC22  220_0402_5%  [R_0402]  89.99 138.67 90 top
RC23  0_0402_5%~D  [R_0402]  90.87 138.67 90 top
RC24  100K_0402_5%  [R_0402]  91.95 139.02 270 top
RC25  1K_0402_5%  [R_0402]  92.84 138.1 90 top
RC26  60.4_0402_1%  [R_0402]  93.73 139.02 270 top
RC27  499_0402_1%  [R_0402]  95.5 138.95 270 top
RC28  1K_0402_5%  [R_0402]  96.39 138.95 270 top
RC29  10K_0402_1%  [R_0402]  97.28 138.95 270 top
RC30  10K_0402_1%  [R_0402]  98.17 138.95 270 top
RC31  2.7K_0402_1%  [R_0402]  80.52 137.15 90 top
RC32  0_0402_5%  [R_0402]  81.41 137.15 90 top
RC33  0_0402_5%  [R_0402]  82.3 137.15 90 top
RC34  0_0402_5%  [R_0402]  49.66 138.22 90 bottom
RC35  1M_0201_5%  [R_0201]  72.67 137.69 0 top
RC36  1K_0402_5%  [R_0402]  49.83 137.91 0 top
RC37  10K_0402_1%  [R_0402]  98.76 136.46 180 top
RC38  10K_0402_5%  [R_0402]  49.83 137.02 0 top
RC39  1K_0402_5%  [R_0402]  98.76 135.57 180 top
RC40  10K_0402_1%  [R_0402]  98.76 133.8 180 top
RC41  0_0201_5%  [R_0201]  51.94 131.68 270 top
RC42  100_0402_1%  [R_0402]  97.41 130.16 90 top
RC43  2.2K_0402_5%  [R_0402]  47.7 128.91 180 top
RC44  100_0402_1%  [R_0402]  97.41 128.39 90 top
RC45  2.2K_0402_5%  [R_0402]  47.7 128.02 180 top
RC46  100K_0402_5%  [R_0402]  50.22 128.11 0 top
RC47  0_0402_1%  [R0402_0OHM]  50.34 126.37 0 top
RC48  4.7K_0402_5%  [R_0402]  77.91 28.47 270 bottom
RC49  2.2K_0402_5%  [R_0402]  51.26 125.46 180 top
RC50  4.7K_0402_5%  [R_0402]  78.8 28.47 270 bottom
RC51  1K_0402_5%  [R_0402]  47.98 124.25 0 top
RC53  100K_0402_5%~D  [R_0402]  45.92 128.02 180 top
RC55  1K_0402_5%  [R_0402]  51.26 124.59 180 top
RC56  10K_0402_5%  [R_0402]  45.01 127.13 0 top
RC58  4.7K_0201_5%  [R_0201]  51.26 123.7 180 top
RC59  10K_0402_5%  [R_0402]  48.51 126.43 0 top
RC60  10K_0201_5%  [R_0201]  47.19 121.79 180 top
RC61  1K_0201_5%  [R_0201]  49.23 121.41 180 top
RC62  0_0201_5%  [R_0201]  51 121.41 180 top
RC63  2.2K_0201_5%  [R_0201]  46.28 120.72 0 top
RC64  150K_0201_1%  [R_0201]  51 120.52 180 top
RC65  2.2K_0201_5%  [R_0201]  50.42 119.76 0 top
RC66  200_0402_1%  [R_0402]  51.7 115.44 180 top
RC67  1K_0402_5%  [R_0402]  50.29 110.5 270 top
RC68  10K_0402_5%  [R_0402]  55.42 108.8 0 top
RC69  1K_0402_5%  [R_0402]  52.7 108.8 270 top
RC70  22_0402_5%  [R_0402]  58.8 108.85 270 top
RC71  15_0402_5%  [R_0402]  59.69 108.85 270 top
RC72  10K_0402_5%  [R_0402]  60.71 107.94 90 top
RC73  10K_0402_5%  [R_0402]  61.85 107.94 90 top
RC74  1K_0402_5%  [R_0402]  62.99 108.85 270 top
RC75  33_0402_5%  [R_0402]  65.91 107.94 90 top
RC76  33_0402_5%  [R_0402]  66.8 107.94 90 top
RC77  33_0402_5%  [R_0402]  67.82 107.94 90 top
RC78  0_0402_5%  [R_0402]  65.04 107.95 180 top
RC80  100K_0402_5%~D  [R_0402]  65.04 107.06 180 top
RC81  4.7K_0402_5%  [R_0402]  66.8 106.16 90 top
RC82  8.2K_0402_5%  [R_0402]  60.71 106.82 270 top
RC83  10K_0402_5%  [R_0402]  17.65 109.02 270 bottom
RC84  8.2K_0402_5%  [R_0402]  57.28 107 180 top
RC85  20K_0201_5%  [R_0201]  64.97 104.6 90 top
RC86  10M_0402_5%  [R_0402]  59.64 104.59 180 top
RC87  0_0402_5%  [R_0402]  60.5 104.59 0 top
RC88  1M_0402_5%  [R_0402]  64.14 103.27 270 top
RC89  20K_0201_5%  [R_0201]  64.98 102.54 0 top
RC90  1K_0402_5%  [R_0402]  63.12 100.32 90 top
RC91  10K_0402_5%  [R_0402]  64.14 101.23 270 top
RC92  1K_0402_5%  [R_0402]  28.38 126.19 270 bottom
RC93  100_0402_1%  [R_0402]  90.92 138.04 90 bottom
RC94  56_0402_1%  [R_0402]  90.03 138.04 90 bottom
RC95  100_0402_1%  [R_0402]  89.14 138.04 90 bottom
RC96  8.2K_0402_5%  [R_0402]  44.72 138.3 180 bottom
RC97  8.2K_0402_5%  [R_0402]  43.8 137.42 0 bottom
RC99  0_0402_5%  [R_0402]  149.22 135.9 270 bottom
RC100  0_0402_5%  [R_0402]  148.21 134.99 90 bottom
RC102  51_0402_5%  [R_0402]  149.28 134.05 0 bottom
RC103  0_0603_5%  [R0603_0OHM]  62.23 134.62 270 bottom
RC104  0_0603_5%  [R_0603]  59.94 133.22 90 bottom
RC105  0_0603_5%  [R_0603]  58.67 133.22 90 bottom
RC106  51_0402_5%  [R_0402]  158.95 133.8 180 bottom
RC107  1.5K_0402_5%  [R_0402]  148.21 133.21 90 bottom
RC108  24.9_0402_1%  [R_0402]  82.88 131.62 90 bottom
RC109  150_0402_5%  [R_0402]  150.19 133.16 180 bottom
RC111  10K_0402_5%  [R_0402]  150.19 132.27 180 bottom
RC112  49.9_0402_1%  [R_0402]  89.03 131.69 90 bottom
RC113  100_0402_1%  [R_0402]  56.45 131.56 90 bottom
RC114  100_0402_1%  [R_0402]  61.47 132.35 270 bottom
RC115  100_0402_1%  [R_0402]  65.2 131.83 0 bottom
RC116  100_0402_1%  [R_0402]  63.42 131.83 0 bottom
RC117  0_0603_5%  [R_0603]  59.94 132.21 270 bottom
RC118  0_0603_5%  [R_0603]  58.67 132.21 270 bottom
RC119  150_0402_5%  [R_0402]  149.28 131.38 0 bottom
RC120  1K_0402_5%  [R_0402]  158.95 131.13 180 bottom
RC121  0_0402_5%  [R_0402]  149.28 130.49 0 bottom
RC122  49.9_0402_1%  [R_0402]  91.69 130.54 90 bottom
RC123  49.9_0402_1%  [R_0402]  90.82 131.7 180 bottom
RC124  100K_0402_5%  [R_0402]  57.4 129.15 90 bottom
RC125  0_0603_5%  [R0603_0OHM]  52.58 131.45 270 bottom
RC126  100K_0402_5%  [R_0402]  59.77 129.1 180 bottom
RC127  1.5K_0402_5%  [R_0402]  62.03 100.32 270 top
RC128  0_0402_1%  [R0402_0OHM]  55.58 128.59 180 bottom
RC129  0_0402_1%  [R0402_0OHM]  60.96 128 90 bottom
RC130  0_0603_5%  [R0603_0OHM]  158.24 126.98 90 bottom
RC131  1K_0402_5%  [R_0402]  149.28 127.83 0 bottom
RC132  1K_0402_5%  [R_0402]  149.28 126.94 0 bottom
RC133  0_0603_5%  [R0603_0OHM]  55.56 125.67 180 bottom
RC134  0_0603_5%  [R0603_0OHM]  64.07 125.6 180 bottom
RC136  0_0402_5%  [R_0402]  119.37 131.7 0 bottom
RC137  113_0402_1%  [R_0402]  55.07 123.13 180 bottom
RC138  0_0402_5%  [R_0402]  119.37 130.81 0 bottom
RC139  0_0603_5%  [R0603_0OHM]  51.75 122.75 180 bottom
RC140  200_0402_1%  [R_0402]  55.07 122.24 180 bottom
RC141  1K_0402_5%  [R_0402]  149.4 122.11 0 bottom
RC142  0_0402_5%  [R_0402]  150.32 121.22 180 bottom
RC143  10K_0402_5%  [R_0402]  59.44 120.92 270 bottom
RC144  1K_0402_5%  [R_0402]  150.32 119.7 180 bottom
RC147  100_0402_1%  [R_0402]  68.4 119.13 180 bottom
RC149  10K_0402_5%  [R_0402]  47.7 125.36 180 top
RC150  0_0402_5%  [R_0402]  44.88 118.24 0 bottom
RC151  51_0402_5%  [R_0402]  149.4 117.92 0 bottom
RC152  100K_0402_5%  [R_0402]  43.94 118.25 270 bottom
RC153  10K_0402_5%  [R_0402]  54.23 117.54 0 bottom
RC154  10K_0402_5%  [R_0402]  44.88 117.35 0 bottom
RC155  100_0402_1%  [R_0402]  67.11 116.91 0 bottom
RC156  0_0402_1%  [R0402_0OHM]  78.08 115.25 90 bottom
RC157  10K_0402_5%  [R_0402]  54.23 116.65 0 bottom
RC158  8.2K_0402_5%  [R_0402]  50.47 115.89 0 bottom
RC159  10K_0402_5%  [R_0402]  54.15 115.38 0 bottom
RC160  49.9_0402_1%  [R_0402]  63.37 115.43 90 bottom
RC161  10K_0402_5%  [R_0402]  54.15 114.49 0 bottom
RC162  10K_0402_5%  [R_0402]  57.96 114.11 0 bottom
RC163  10K_0402_5%  [R_0402]  54.15 113.6 0 bottom
RC164  200_0402_1%  [R_0402]  65.79 113.43 270 bottom
RC165  162_0402_1%  [R_0402]  64.77 113.43 270 bottom
RC166  80.6_0402_1%  [R_0402]  63.75 113.43 270 bottom
RC167  49.9_0402_1%  [R_0402]  62.74 113.43 270 bottom
RC168  10K_0402_5%  [R_0402]  54.15 112.71 0 bottom
RC169  33_0402_5%  [R_0402]  51.49 101.53 270 bottom
RC170  0_0402_1%  [R0402_0OHM]  35.18 79.77 270 bottom
RC178  2.2K_0402_5%  [R_0402]  47.7 126.25 180 top
RC179  2.2K_0402_5%  [R_0402]  47.7 127.14 180 top
RC180  10K_0201_5%  [R_0201]  46.99 100.86 90 top
RC181  10K_0201_5%  [R_0201]  49.05 123.51 180 top
RC182  10K_0201_5%  [R_0201]  13.55 137.9 180 bottom
RC183  10K_0201_5%  [R_0201]  7.76 137.01 180 bottom
RC185  0_0603_5%  [R_0603]  47.94 121.48 0 bottom
RC186  0_0603_5%  [R_0603]  47.94 120.21 0 bottom
RC187  33_0201_1%  [R_0201]  143.22 129.48 0 bottom
RC188  1M_0201_5%  [R_0201]  26.54 128.17 90 bottom
RC189  10K_0402_5%  [R_0402]  148.34 126.93 90 bottom
RC190  49.9K_0402_1%  [R_0402]  48.01 123.43 90 bottom
RC191  49.9K_0402_1%  [R_0402]  48.01 126.13 270 bottom
RC192  100K_0201_5%  [R_0201]  57.91 109.89 270 top
RC193  100K_0201_5%  [R_0201]  57.37 113.22 0 bottom
RC194  100K_0201_5%  [R_0201]  52.54 128.84 0 bottom
RC195  10K_0201_5%  [R_0201]  51.09 90.49 180 bottom
RC196  0_0201_5%  [R_0201]  46.44 123.76 0 top
RC197  0_0402_5%  [R_0402]  49.03 125.87 270 bottom
RC198  0_0201_5%  [R_0201]  46.44 124.4 0 top
RC199  10K_0402_5%  [R_0402]  49.03 123.2 90 bottom
RC200  100K_0402_5%~D  [R_0402]  43.43 130.44 270 bottom
RC202  10K_0402_5%  [R_0402]  29.34 107.51 180 top
RC204  10K_0402_5%  [R_0402]  61.75 138.95 270 top
RC205  10K_0201_5%  [R_0201]  42.11 122.91 0 top
RC206  10K_0201_5%  [R_0201]  42.11 123.5 0 top
RC374  1M_0201_1%  [R_0201]  50.36 132.59 270 top
RC377  33_0201_1%  [R_0201]  50.94 132.01 90 top
RC378  33_0201_1%  [R_0201]  50.28 133.19 0 top
RC380  33_0201_1%  [R_0201]  74.43 137.69 180 top
RC381  33_0201_1%  [R_0201]  73.25 137.11 180 top
RC383  15_0402_5%  [R_0402]  56.64 105.22 0 top
RC384  15_0402_5%  [R_0402]  57.02 106.11 0 top
RC385  15_0402_5%  [R_0402]  56.64 104.33 0 top
RC386  15_0402_5%  [R_0402]  56.64 103.44 0 top
RC389  60.4_0402_1%  [R_0402]  88.9 141.04 180 top
RC391  220K_0201_5%  [R_0201]  57.35 112.14 180 bottom
RC392  100K_0201_5%  [R_0201]  60.52 113.26 270 bottom
RC393  100K_0201_5%  [R_0201]  64 86.88 0 top
RC394  0_0402_5%  [R_0402]  55.12 106.88 270 bottom
RC395  0_0402_5%  [R_0402]  56.01 106.88 270 bottom
RC396  100K_0201_5%  [R_0201]  54.28 118.43 0 bottom
RC397  10K_0201_1%  [R_0201]  62.74 111.19 90 bottom
RC398  0_0201_5%  [R_0201]  50.08 115.41 90 top
RC399  0_0201_5%  [R_0201]  45.85 124.4 180 top
RD1  240_0402_1%  [R_0402]  91.44 106.16 90 top
RD2  240_0402_1%  [R_0402]  92.33 106.16 90 top
RD3  24.9_0402_1%  [R_0402]  69.53 99.07 0 bottom
RD4  8.2K_0402_1%  [R_0402]  72.58 97.87 180 top
RD5  10_0402_1%~D  [R_0402]  71.31 98.15 0 bottom
RD6  8.2K_0402_1%  [R_0402]  72.58 96.08 90 top
RD7  240_0402_1%  [R_0402]  86.88 89.86 0 top
RD8  240_0402_1%  [R_0402]  86.88 90.74 0 top
RD9  24.9_0402_1%  [R_0402]  89.41 108.26 90 bottom
RD10  4.99_0402_1%~D  [R_0402]  91.12 107.39 270 bottom
RD11  8.2K_0402_1%  [R_0402]  90.25 106.49 180 bottom
RD12  8.2K_0402_1%  [R_0402]  92.15 104.84 180 bottom
RD13  240_0402_1%  [R_0402]  82.42 104.9 90 bottom
RD14  240_0402_1%  [R_0402]  81.53 104.9 90 bottom
RD15  10_0402_1%~D  [R_0402]  103.63 100.34 270 top
RD16  8.2K_0402_1%  [R_0402]  102.67 98.49 0 top
RD17  24.9_0402_1%  [R_0402]  105.46 99.38 0 top
RD18  8.2K_0402_1%  [R_0402]  102.74 100.34 270 top
RD19  240_0402_1%  [R_0402]  92.46 90.24 0 bottom
RD20  240_0402_1%  [R_0402]  91.26 90.24 180 bottom
RD21  68_0201_1%  [R_0201]  88.66 103.9 180 bottom
RD22  68_0201_1%  [R_0201]  86.77 92.27 0 bottom
RD23  68_0201_1%  [R_0201]  88.66 103.33 180 bottom
RD24  68_0201_1%  [R_0201]  86.77 93.41 0 bottom
RD25  68_0201_1%  [R_0201]  88.66 102.19 180 bottom
RD26  68_0201_1%  [R_0201]  86.77 94.55 0 bottom
RD27  68_0201_1%  [R_0201]  88.66 102.76 180 bottom
RD28  68_0201_1%  [R_0201]  86.77 92.84 0 bottom
RD29  68_0201_1%  [R_0201]  88.66 101.61 180 bottom
RD30  68_0201_1%  [R_0201]  86.77 93.98 0 bottom
RD31  68_0201_1%  [R_0201]  88.53 94.92 180 bottom
RD32  68_0201_1%  [R_0201]  86.83 101.47 0 bottom
RD33  68_0201_1%  [R_0201]  88.53 93.78 180 bottom
RD34  68_0201_1%  [R_0201]  86.83 102.62 0 bottom
RD35  68_0201_1%  [R_0201]  88.53 94.35 180 bottom
RD36  68_0201_1%  [R_0201]  86.83 102.05 0 bottom
RD37  68_0201_1%  [R_0201]  88.53 93.21 180 bottom
RD38  68_0201_1%  [R_0201]  86.83 103.19 0 bottom
RD39  68_0201_1%  [R_0201]  88.53 92.64 180 bottom
RD40  68_0201_1%  [R_0201]  86.83 103.76 0 bottom
RD41  68_0201_1%  [R_0201]  88.73 92.7 180 top
RD42  68_0201_1%  [R_0201]  86.96 103.32 0 top
RD43  68_0201_1%  [R_0201]  88.73 93.26 180 top
RD44  68_0201_1%  [R_0201]  86.96 102.74 0 top
RD45  68_0201_1%  [R_0201]  88.74 94.41 180 top
RD46  68_0201_1%  [R_0201]  86.96 101.6 0 top
RD47  68_0201_1%  [R_0201]  88.73 93.83 180 top
RD48  68_0201_1%  [R_0201]  86.96 102.17 0 top
RD49  68_0201_1%  [R_0201]  88.74 94.98 180 top
RD50  68_0201_1%  [R_0201]  86.96 101.03 0 top
RD51  68_0201_1%  [R_0201]  88.72 100.36 180 top
RD52  68_0201_1%  [R_0201]  86.9 95 0 top
RD53  68_0201_1%  [R_0201]  88.72 101.5 180 top
RD54  68_0201_1%  [R_0201]  86.9 93.73 0 top
RD55  68_0201_1%  [R_0201]  88.72 100.93 180 top
RD56  68_0201_1%  [R_0201]  86.9 94.36 0 top
RD57  68_0201_1%  [R_0201]  88.72 102.07 180 top
RD58  68_0201_1%  [R_0201]  86.9 93.16 0 top
RD59  68_0201_1%  [R_0201]  88.72 102.64 180 top
RD60  68_0201_1%  [R_0201]  86.9 92.58 0 top
RD61  80.6_0201_1%~D  [R_0201]  88.67 100.97 180 bottom
RD62  80.6_0201_1%~D  [R_0201]  86.77 95.12 0 bottom
RD63  80.6_0201_1%~D  [R_0201]  88.73 97.47 180 top
RD64  80.6_0201_1%~D  [R_0201]  86.96 100.46 0 top
RD65  80.6_0201_1%~D  [R_0201]  88.67 100.33 180 bottom
RD66  80.6_0201_1%~D  [R_0201]  86.77 96.71 0 bottom
RD67  80.6_0201_1%~D  [R_0201]  88.53 95.49 180 bottom
RD68  80.6_0201_1%~D  [R_0201]  86.77 96.08 0 bottom
RD69  80.6_0201_1%~D  [R_0201]  88.72 98.05 180 top
RD70  80.6_0201_1%~D  [R_0201]  86.96 98.74 0 top
RD71  80.6_0201_1%~D  [R_0201]  88.72 98.62 180 top
RD72  80.6_0201_1%~D  [R_0201]  86.96 99.32 0 top
RD73  80.6_0201_1%~D  [R_0201]  88.74 92.12 180 top
RD74  80.6_0201_1%~D  [R_0201]  86.96 99.89 0 top
RD75  37.4_0201_1%~D  [R_0201]  88.53 96.07 180 bottom
RD76  37.4_0201_1%~D  [R_0201]  86.77 99.7 0 bottom
RD77  37.4_0201_1%~D  [R_0201]  88.53 96.64 180 bottom
RD78  37.4_0201_1%~D  [R_0201]  86.77 99.13 0 bottom
RD79  37.4_0201_1%~D  [R_0201]  88.72 99.76 180 top
RD80  37.4_0201_1%~D  [R_0201]  86.96 97.47 0 top
RD81  37.4_0201_1%~D  [R_0201]  88.72 99.19 180 top
RD82  37.4_0201_1%~D  [R_0201]  86.96 98.11 0 top
RE1  10K_0201_5%  [R_0201]  33.22 88.25 90 top
RE2  10K_0201_5%  [R_0201]  34.49 88.25 90 top
RE3  10K_0201_5%  [R_0201]  33.86 88.25 90 top
RE4  10K_0201_5%  [R_0201]  35.12 88.25 90 top
RE5  10K_0201_5%  [R_0201]  36.82 88.25 90 top
RE6  10K_0201_5%  [R_0201]  37.53 88.25 90 top
RE7  10K_0201_5%  [R_0201]  38.2 88.25 90 top
RE8  10K_0201_5%  [R_0201]  38.91 88.25 90 top
RE9  49.9_0402_1%  [R_0402]  40.34 88.38 90 top
RE10  0_0402_5%~D  [R_0402]  35.51 121.6 180 bottom
RE11  0_0603_5%  [R0603_0OHM]  16.64 115.76 90 bottom
RE12  0_0402_5%  [R_0402]  65.15 101.23 270 bottom
RE13  0_0402_5%~D  [R_0402]  37.01 120.97 0 bottom
RE14  100K_0402_5%  [R_0402]  36.14 120.72 180 bottom
RE15  4.3K_0402_5%  [R_0402]  20.18 124.21 0 bottom
RE16  100K_0201_5%  [R_0201]  63.33 103.19 0 bottom
RE17  100K_0201_5%  [R_0201]  24.07 124.11 90 bottom
RE19  0_0402_1%  [R0402_0OHM]  34.1 107.1 180 bottom
RE20  100K_0201_5%  [R_0201]  26.97 120.55 90 bottom
RE24  100K_0201_5%  [R_0201]  18.03 113.1 0 bottom
RE25  100K_0201_5%  [R_0201]  32.99 112.4 180 bottom
RE26  2.2K_0201_5%  [R_0201]  34.2 112.4 180 bottom
RE27  100K_0201_5%  [R_0201]  34.92 107 270 bottom
RE29  100K_0402_5%  [R_0402]  34.92 116.98 270 bottom
RE30  1K_0201_5%  [R_0201]  30.86 104.69 270 bottom
RE31  100K_0201_5%  [R_0201]  19.35 105.98 90 bottom
RE32  1K_0201_5%  [R_0201]  30.29 104.69 270 bottom
RE33  10K_0201_5%  [R_0201]  24.07 122.28 270 bottom
RE35  2.2K_0201_5%  [R_0201]  18.1 107 180 bottom
RE36  0_0402_5%~D  [R_0402]  34.92 114.29 90 bottom
RE38  2.2K_0201_5%  [R_0201]  18.12 106.43 180 bottom
RE40  100K_0201_5%  [R_0201]  29.07 103.47 180 bottom
RE41  SHORT PADS  [SHORTPADS]  25.02 121.16 90 bottom
RE42  100K_0201_5%  [R_0201]  24.07 121.07 270 bottom
RE44  100K_0402_5%  [R_0402]  34.92 113.43 270 bottom
RE45  1K_0201_5%  [R_0201]  32.64 112.97 0 bottom
RE46  1K_0201_5%  [R_0201]  32.51 116.19 0 bottom
RE47  0_0402_1%  [R0402_0OHM]  17.6 112.21 0 bottom
RE48  100K_0402_5%  [R_0402]  35.88 110.06 270 bottom
RE49  43_0201_5%  [R_0201]  24.07 122.9 90 bottom
RE50  75_0402_5%  [R_0402]  27.5 125.27 90 bottom
RE51  100K_0201_5%  [R_0201]  16.31 111.83 0 bottom
RE52  100K_0201_5%  [R_0201]  33.91 113.55 270 bottom
RE53  100K_0201_5%  [R_0201]  16.73 118.11 0 bottom
RE54  10K_0201_5%  [R_0201]  27.81 122.77 0 bottom
RE55  10K_0201_5%  [R_0201]  22.35 106.62 270 bottom
RE56  100K_0201_5%  [R_0201]  18.03 115.64 0 bottom
RE58  1.96K_0402_1%  [R_0402]  30.13 122.38 90 bottom
RE61  10K_0201_5%  [R_0201]  26.97 121.74 90 bottom
RE62  10K_0201_5%  [R_0201]  18.63 113.67 180 bottom
RE63  100K_0201_5%  [R_0201]  18.03 117.92 0 bottom
RE64  10K_0201_5%  [R_0201]  29.16 104.66 270 bottom
RE65  10K_0201_5%  [R_0201]  18.11 111.49 180 bottom
RE67  100K_0201_5%  [R_0201]  17.31 119.83 180 bottom
RE68  1K_0201_5%  [R_0201]  32.64 113.55 0 bottom
RE69  220K_0201_5%  [R_0201]  31.43 104.1 90 bottom
RE70  1K_0201_5%  [R_0201]  32.51 115.61 0 bottom
RE97  0_0402_5%  [R_0402]  37.66 109.15 90 bottom
RE98  0_0402_5%  [R_0402]  36.77 109.15 90 bottom
RE99  0_0402_5%  [R_0402]  22.87 124.21 180 bottom
RE100  0_0402_5%  [R_0402]  22.87 125.1 180 bottom
RE110  2.2K_0201_5%  [R_0201]  28.47 122.2 270 bottom
RE111  2.2K_0201_5%  [R_0201]  28.32 120.33 90 bottom
RE112  100K_0201_5%  [R_0201]  30.3 106.66 270 bottom
RE113  10K_0201_5%  [R_0201]  43.17 104.28 270 top
RE114  0_0402_5%  [R_0402]  25.53 126.35 90 bottom
RE115  100K_0201_5%  [R_0201]  16.73 118.68 0 bottom
RE116  10K_0201_5%  [R_0201]  22.99 106.62 270 bottom
RE117  100K_0201_5%  [R_0201]  28.45 105.73 90 bottom
RE118  100K_0201_5%  [R_0201]  27.89 121.62 90 bottom
RE119  0_0201_5%  [R0201_0OHM]  27.69 120.96 270 bottom
RE120  0_0402_5%  [R_0402]  26.42 126.35 90 bottom
RE121  0_0201_5%  [R0201_0OHM]  19.94 106.62 270 bottom
RE122  1M_0201_5%  [R_0201]  136.54 94.39 0 top
RE123  4.99K_0201_1%  [R_0201]  24.74 75.36 180 bottom
RE124  300_0402_5%  [R_0402]  18.22 105.73 270 bottom
RE125  300_0402_5%  [R_0402]  20.69 105.74 0 bottom
RE141  100K_0402_5%  [R_0402]  36.8 108.27 0 bottom
RE142  100K_0402_5%  [R_0402]  29.21 106.49 270 bottom
RE152  1K_0402_5%  [R_0402]  32 106.63 270 bottom
RE154  100K_0402_5%  [R_0402]  31.11 106.63 270 bottom
RE157  10K_0402_5%  [R_0402]  25.65 107.51 180 top
RE168  10K_0402_5%  [R_0402]  18.17 101.07 0 bottom
RE172  33_0402_5%  [R_0402]  25.08 103.84 270 bottom
RE174  100K_0402_5%  [R_0402]  16.47 104.67 90 bottom
RE183  10K_0402_5%  [R_0402]  17.35 101.07 180 bottom
RE193  0_0402_5%  [R_0402]  56.24 94.55 270 top
RE194  100_0402_1%  [R_0402]  26.57 104.78 180 bottom
RE195  0_0603_5%  [R_0603]  17.02 110.05 0 bottom
RE196  240K_0402_5%  [R_0402]  28.32 123.51 180 bottom
RE215  8.2K_0402_5%  [R_0402]  19.89 123.32 180 bottom
RE219  2.2K_0402_5%  [R_0402]  19.89 121.54 180 bottom
RE222  0_0402_5%  [R_0402]  18.97 120.65 0 bottom
RE245  0_0201_5%  [R0201_0OHM]  16.31 112.59 0 bottom
RE246  10K_0402_5%  [R_0402]  31.14 120.64 90 bottom
RE247  100K_0402_5%  [R_0402]  16.41 113.41 0 bottom
RE248  0_0402_1%  [R0402_0OHM]  29.25 123.3 270 bottom
RE250  100K_0201_5%  [R_0201]  29.72 104.1 90 bottom
RE251  100K_0201_5%  [R_0201]  17.31 119.25 180 bottom
RE252  0_0402_1%  [R0402_0OHM]  31.17 128.65 0 bottom
RE253  100K_0402_5%  [R_0402]  32.08 127.76 180 bottom
RE258  1M_0201_5%  [R_0201]  19.79 101.68 270 bottom
RE259  1M_0201_5%  [R_0201]  32.69 104.08 0 bottom
RE261  0_0201_5%  [R0201_0OHM]  18.67 119.06 180 bottom
RE262  100K_0201_5%  [R_0201]  27.86 104.84 180 bottom
RE264  62K_0402_1%  [R_0402]  27.74 103.82 270 bottom
RE265  43K_0402_1%  [R_0402]  18.53 109.02 270 bottom
RE266  100K_0201_5%  [R_0201]  29.54 108.65 180 top
RE267  100K_0201_5%  [R_0201]  123.71 90.96 270 top
RE268  100K_0201_5%  [R_0201]  124.51 90.96 270 top
RE269  2.2K_0201_5%  [R_0201]  28.19 110.94 0 top
RE270  2.2K_0201_5%  [R_0201]  28.19 110.3 0 top
RH1  2.2K_0201_5%  [R_0201]  118.28 173.74 180 top
RH2  2.2K_0201_5%  [R_0201]  118.28 173.1 180 top
RH3  49.9K_0201_1%  [R_0201]  48.7 122.21 180 top
RH4  49.9K_0201_1%  [R_0201]  50.29 122.26 0 top
RH5  10K_0201_5%  [R_0201]  43.56 121.5 90 top
RH6  10K_0402_5%  [R_0402]  18.57 116.52 180 bottom
RH7  100K_0201_5%  [R_0201]  44.83 121.5 90 top
RH8  10K_0201_5%  [R_0201]  45.47 121.5 90 top
RH9  10K_0402_5%  [R_0402]  42.3 120.46 180 top
RH10  10K_0402_5%  [R_0402]  44.08 120.46 180 top
RH11  100K_0201_5%  [R_0201]  49.23 120.52 180 top
RH12  10K_0402_5%  [R_0402]  42.3 119.45 180 top
RH13  10K_0402_5%  [R_0402]  44.08 119.45 180 top
RH14  100K_0201_5%  [R_0201]  48.64 119.91 0 top
